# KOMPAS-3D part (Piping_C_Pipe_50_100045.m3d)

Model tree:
1. Plane XY
2. Plane ZX
3. Plane ZY
4. X Axis
5. Y Axis
6. Z Axis
7. Origin
8. Path  (labels: Труба Dy 50)
9. Plane of section
10. Section of pipe
11. Pipe
     Толщина стенки 1 = 1

Referenced files in C:\Program Files\ASCON\KOMPAS-3D V10\Libs\Piping\Models\Tanks\: Tanks.a3d
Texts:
  Pipe Dn 50
  Steel ASTM A295
  Three Point Plane
  Plane at Angle
  Line and Point Plane
  Axis through Two Vertices
  Axis of Feature
  Axis of Conical Surface
  Axis through Edge
  Приклеить элемент выдавливания
  Приклеить элемент вращения
  Приклеить кинематический элемент
  Приклеить элемент по сечениям
  Trim by Surface
  Trim by Sketch
  Feature with No History
  Intersection Axis of Two Planes
  Two Line Plane
  Line and Face Plane
  Bend by line
  Hole in sheet body
  Cut in sheet body
  Point in CM
  Linear Dimension from Line to Point
  Surface Finish Symbol
  Geometric Tolerance Symbol
  Текст на чертеже
  Линия-выноска #1
  Линия-выноска #2
  Линия-выноска #3
  Отклонения формы и база
  Марка координационной оси
  Марка/позиционное обозначение с линией-выноской
  Марка/позиционное обозначение на линии
  Марка/позиционное обозначение без линии-выноски
  Труба Dy 50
